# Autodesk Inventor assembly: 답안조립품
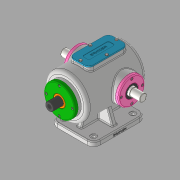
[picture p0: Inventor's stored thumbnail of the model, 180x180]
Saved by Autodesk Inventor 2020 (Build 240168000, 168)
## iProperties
Created: 2021-11
Part Number: 답안조립품
Document SubType Name: Assembly
Designer: Administrator
Author: Administrator
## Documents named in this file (14)
- C:\Users\Administrator\Desktop\711106V1024\답안조립품.iam
- C:\Users\Administrator\Desktop\711106V1024\본체.ipt
- C:\Users\Administrator\Desktop\711106V1024\베어링 6205.ipt
- 베어링 6205.ipt
- C:\Users\Administrator\Desktop\711106V1024\볼트 M4x0.7.ipt
- C:\Users\Administrator\Desktop\711106V1024\부시.ipt
- C:\Users\Administrator\Desktop\711106V1024\상부커버.ipt
- C:\Users\Administrator\Desktop\711106V1024\슬라이드 커버.ipt
- C:\Users\Administrator\Desktop\711106V1024\슬라이드.ipt
- C:\Users\Administrator\Desktop\711106V1024\오일실.ipt
- 오일실.ipt
- C:\Users\Administrator\Desktop\711106V1024\육각머리볼트 M4.ipt
- C:\Users\Administrator\Desktop\711106V1024\축 커버.ipt
- C:\Users\Administrator\Desktop\711106V1024\편심축.ipt
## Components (12 placed, 1 different names)
1. M4x0.7:2 — 각도:1
2. M4x0.7:3
3. M4x0.7:4
4. M4x0.7:5
5. M4x0.7:1 — 각도:2
6. M4x0.7:6
7. M4x0.7:7
8. M4x0.7:8
9. M4x0.7:9 — 각도:3
10. M4x0.7:10
11. M4x0.7:11
12. M4x0.7:12
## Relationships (3: Angle 3)
- 각도:1 [Angle]: M4x0.7:2
- 각도:2 [Angle]: M4x0.7:1
- 각도:3 [Angle]: M4x0.7:9
